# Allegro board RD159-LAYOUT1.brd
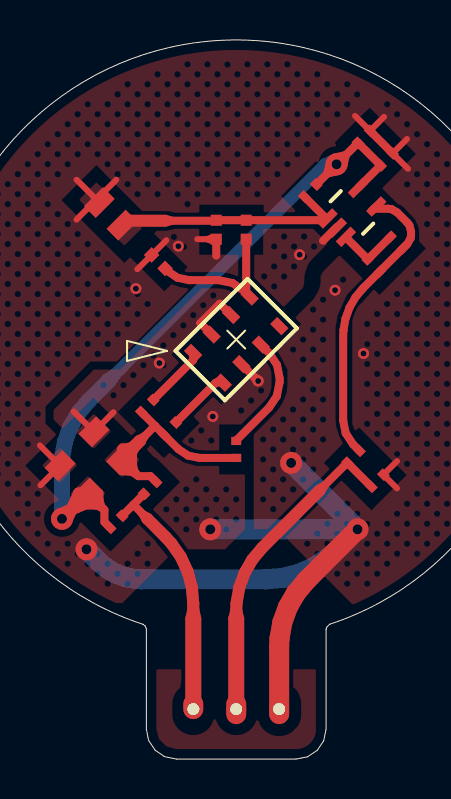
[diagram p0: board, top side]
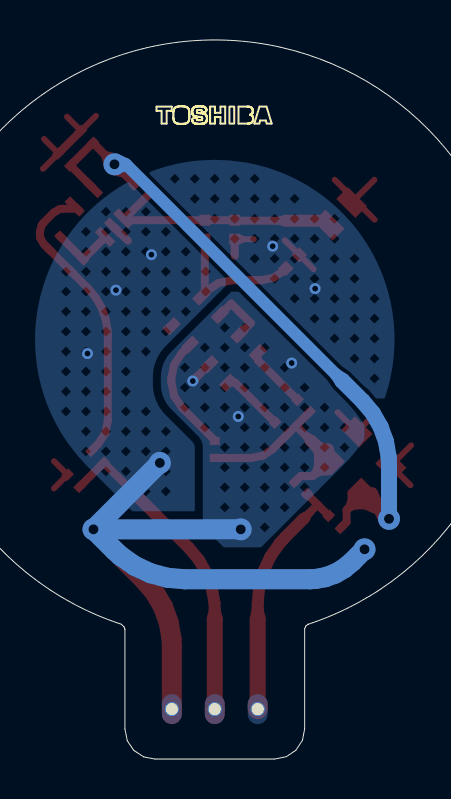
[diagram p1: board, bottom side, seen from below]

Outline 9.35 x 36 mm; copper layers: TOP, BOTTOM. Coordinates in mm from the lower left corner of the outline.
Outline path: 0,6.75 arc(4.67,36) 9.35,6.75 9.22,6.62 9.19,6.54 9.18,6.49 9.18,1.5 9.06,0.91 8.74,0.44 8.24,0.11 7.68,0 1.68,0 1.09,0.12 0.62,0.44 0.29,0.94 0.18,1.5 0.18,6.53 0.11,6.66 0.01,6.74 0,6.75

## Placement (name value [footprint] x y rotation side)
C1  -  [KC00060ATS01]  -1.76 15.7 315 top
C2  -  [DC834K0ACP]  12.7 25.84 315 top
C3  -  [KC00050ACF01]  11.75 13.93 225 top
C4  -  [KC00050ACF01]  12.21 30.02 225 top
C5  -  [KC00050ACF01]  11.08 31.15 225 top
C6  -  [KC00060ATS01]  -3.45 14 315 top
C7  -  [DC810K]  -1.61 27.3 135 top
NOREF  -  []  8.44 30.96 0 top
R1  -  [DR824K0ACF01]  4.68 15.5 90 top
R2  -  [DR824K0ACF01]  1.35 16.55 45 top
R3  -  [DR824K0ACF01]  0.22 17.68 45 top
R4  -  [KC00050ACF01]  0.36 13.57 225 top
R5  -  [DR824K0ACP]  11.57 24.71 315 top
R6  -  [DR824K0ACP]  -1.34 11.88 225 top
R7  -  [DR824K0ACF01]  10.55 15.13 225 top
R8  -  [KCK02021AKP]  5.18 26.5 90 top
R9  -  [KCK02021AKP]  3.68 26.5 270 top
R10  -  [KCK02021AKP]  0.78 24.9 135 top
R11  -  [KC00050ACP]  8.39 28.46 45 top
TP1  -  [DCK7F1]  2.53 2.5 0 top
TP2  -  [DCK7F1]  4.68 2.5 0 top
TP3  -  [DCK7F1]  6.83 2.5 0 top
U1  -  [LAP02741AKP]  4.68 21 45 top
U2  -  [MMS00380AKF]  10.47 27.36 315 top

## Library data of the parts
C1 C6 = GDM030002136: alternate symbols: (T:KC00060ATS01;B:KC00060BTS01,KC00060BFS01)
C2 = G36030133418: alternate symbols: (T:DC834K0ACP;B:DC834K0BCP)
C3 = GDM030000207: alternate symbols: (T:KC00050ACF01;B:KC00050BCF01)
C4 = GDM030002097: alternate symbols: (T:KC00050ACF01;B:KC00050BCF01)
C5 = GDM030002515: alternate symbols: (T:KC00050ACF01;B:KC00050BCF01)
C7 = GDM030000019: alternate symbols: (T:DC810K;B:DC910K)
R1-R3 R7 = GDM010001350: alternate symbols: (T:DR824K0ACF01;B:DR824K0BCF01)
R4 = GDM010003904: alternate symbols: (T:KC00050ACF01;B:KC00050BCF01)
R5 = G36010118169: alternate symbols: (T:DR824K0ACP;B:DR824K0BCP)
R6 = G36010118534: alternate symbols: (T:DR824K0ACP;B:DR824K0BCP)
R8-R10 = GDM010003025: alternate symbols: (T:KCK02021AKP;B:KCK02021BKP)
R11 = GDM010002207: alternate symbols: (T:KC00050ACP;B:KC00050BCP)
TP1-TP3 = DCK7F1: alternate symbols: (T:DCK7F1;B:DCK7B1)
U1 = K47S002B: alternate symbols: (T:LAP02741AKP;B:LAP02741BKP)
U2 = K47S002A: alternate symbols: (T:MMS00380AKF;B:MMS00380BKF)

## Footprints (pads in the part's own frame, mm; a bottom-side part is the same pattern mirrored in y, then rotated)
DC810K
  rect 0.83x1.35 smd: 1(-0.8,0) 2(0.8,0)
DC834K0ACP
  rect 0.41x0.5 smd: 1(-0.425,0) 2(0.425,0)
DCK7F1
  round 0.711 hole 0.6: 1(0,0)
DR824K0ACF01
  rect 0.41x0.5 smd: 1(-0.425,0) 2(0.425,0)
DR824K0ACP
  rect 0.41x0.5 smd: 1(-0.425,0) 2(0.425,0)
KC00050ACF01
  rect 0.41x0.5 smd: 1(-0.425,0) 2(0.425,0)
KC00050ACP
  rect 0.41x0.5 smd: 1(-0.425,0) 2(0.425,0)
KC00060ATS01
  rect 0.95x1.25 smd: 1(-0.975,0) 2(0.975,0)
KCK02021AKP
  rect 0.55x0.55 smd: 1(-0.475,0) 2(0.475,0)
LAP02741AKP
  rect 0.5x0.8 smd: 1(-2,1.05) 2(-0.69,1.05) 3(0.69,1.05) 4(2,1.05) 5(2,-1.05) 6(0.69,-1.05) 7(-0.69,-1.05) 8(-2,-1.05)
MMS00380AKF
  rect 0.4x1.05 smd: 1(-0.65,-1.075) 2(0,-1.075) 3(0.65,-1.075) 4(0.65,1.075) 5(-0.65,1.075)

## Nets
GND: C1.1(TP-1) C3.1(TP-1) C4.1(TP-1) C5.1(TP-1) C6.1(TP-1) C7.2(TP-1) R9.2(TP-1) R10.2(TP-1) TP3.1 U1.2 U1.3 U1.7 U2.2
VCC: R4.2(TP-1) R6.1(TP-1) TP1.1
SENS: C3.2(TP-1) R7.2(TP-1) TP2.1
SIG14: C4.2(TP-1) C5.2(TP-1) C6.2(TP-1) R6.2(TP-1) R11.2(TP-1) U2.5
SIG18: R8.1(TP-1) R10.1(TP-1) U1.4
SIG19: C7.1(TP-1) R8.2(TP-1) R9.1(TP-1) R11.1(TP-1) U2.1
SIG21: C2.1(TP-1) R5.1(TP-1) U1.5 U2.3
SIG22: C1.2(TP-1) R1.1(TP-1) R2.1(TP-1) R3.1(TP-1) R4.1(TP-1)
SIG23: C2.2(TP-1) R5.2(TP-1) R7.1(TP-1) U2.4
SIG26: R3.2(TP-1) U1.1
SIG27: R2.2(TP-1) U1.8
SIG28: R1.2(TP-1) U1.6

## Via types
v1: diameter 1.1, hole 0.5, TOP to BOTTOM, 6 vias
v2: diameter 0.55, hole 0.3, TOP to BOTTOM, 8 vias

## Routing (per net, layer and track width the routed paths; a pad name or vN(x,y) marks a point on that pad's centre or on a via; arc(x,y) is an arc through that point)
GND: length 64.5
  TOP w0.3: -3.46,17.4 C1.1 -1.47,17.36 ; 12.73,13.55 C3.1 12.73,14.91 ; 10.63,32.2 C5.1 12.08,32.15 ; 3.51,26.02 2.73,26.02 ; -5.15,15.7 C6.1 -5.12,13.71 ; -0.27,24.52 R10.2 1.18,25.97 ; C7.2 -2.32,28 ; -2.32,28 -3.32,27 ; -2.32,28 -3.32,29 ; -2.32,28 -1.33,29 ; 13.28,29.55 C4.1 13.23,31.04
  TOP w0.4: U1.3 3.85,22.8 2.88,21.82 U1.2 ; v2(5.78,18.93) 4.83,19.88 ; C5.1 C4.1 ; 9.72,26.64 9.03,25.95 ; R9.2 3.68,25.2
  TOP w0.508: R9.2 3.51,26.02
  TOP w1: v1(10.75,11.5) 8.2,8.95 7.68,8.32 7.27,7.61 6.99,6.84 6.84,6.04 6.83,5.63 TP3.1 6.83,2.25
  BOTTOM w1: v1(10.75,11.5) 9.72,10.46 9.39,10.17 8.68,9.67 7.89,9.3 7.05,9.08 6.18,9 -0.08,9 -0.34,9.01 -0.86,9.1 -1.35,9.28 -1.8,9.54 -2.2,9.88 v1(-2.82,10.5) ; v1(10.75,11.5) v1(7.43,14.82) ; v1(10.75,11.5) v1(3.38,11.5)
  vias: v2(-0.35,23.55) v2(0.83,19.82) v2(1.78,25.68) v2(3.5,17.15) v2(7.85,25.25) v2(9.63,23.48) v2(11.05,20.3)
VCC: length 12.8
  TOP w0.4: 0.23,12.03 -0.1,12.35 ; -0.47,12.74 -0.09,12.35 ; -0.47,12.74 0.06,13.27 ; -0.47,12.74 R6.1
  TOP w0.6: 0.23,12.03 1.15,11.1 1.43,10.8 1.9,10.13 2.24,9.39 2.45,8.59 2.53,7.78 2.53,7
  TOP w0.8: 2.53,2.75 2.53,7
  TOP w1: TP1.1 2.53,2.75
SENS: length 16.4
  TOP w0.4: C3.2 10.25,14.83 ; 8.85,13.45 10.24,14.84
  TOP w0.6: 4.68,7 4.68,7.42 4.69,7.81 4.83,8.58 5.09,9.31 5.48,9.99 5.98,10.58 8.85,13.45
  TOP w0.8: 4.68,2.75 4.68,7
  TOP w1: 4.68,2.75 TP2.1 4.68,2.25
SIG14: length 40.4
  TOP w0.4: -2.17,13.31 C6.2 -1.99,12.53 ; -2.75,12.7 -2.41,12.7 -2.25,12.67 -1.96,12.51 ; -1.96,12.51 -1.92,12.47 -1.92,11.86 -1.64,11.57 ; -1.96,12.51 -1.99,12.53 ; R11.2 v1(9.7,29.77) C5.2 C4.2 10.81,28.62 ; -1.99,12.53 -2.09,12.67 -2.17,12.98 -2.17,13.3
  TOP w0.6: v1(-4.05,12.03) -3.85,11.9 -3.2,13.3 C6.2 ; v1(-4.05,12.03) C6.2 ; v1(-4.05,12.03) -4.15,12.25 -2.75,12.85 C6.2
  BOTTOM w0.6: -1.72,18.93 9.13,29.77 v1(9.7,29.77)
  BOTTOM w0.8: -1.72,18.93 -2.73,17.92 -3.24,17.32 -3.63,16.64 -3.9,15.9 -4.03,15.13 -4.05,14.73 v1(-4.05,12.03)
SIG18: length 7.6
  TOP w0.4: R8.1 5.18,23.33 U1.4 5.06,23.45 4.49,23.83 3.78,23.98 2.32,23.98 1.74,24.09 1.26,24.41 R10.1
SIG19: length 12
  TOP w0.4: 9.26,27.1 9.13,26.98 R8.2 R9.1 ; 1.1,26.95 3.68,26.95 ; R11.1 9.19,27.05
  TOP w0.6: 1.1,26.95 -0.83,26.95 C7.1
SIG21: length 3.1
  TOP w0.4: C2.1 R5.1 10.18,26.11
SIG22: length 14.2
  TOP w0.4: -0.49,15.04 -0.49,14.69 -0.4,14.37 -0.3,14.24 ; -0.28,14.21 -0.3,14.24 ; -0.28,14.21 -0.23,14.16 0.38,14.16 R4.1 ; -0.28,14.21 -0.56,14.38 -0.73,14.4 -1.05,14.4 ; -0.3,14.24 C1.2 ; R3.1 0.61,16.68 ; 0.61,16.68 -0.15,15.93 ; 0.61,16.68 R2.1 1.78,15.51 2.26,15.19 2.84,15.07 R1.1
  TOP w0.6: -1,15.5 -0.84,15.5 -0.52,15.59 -0.39,15.69 -0.15,15.93 ; C1.2 -0.15,15.93 ; -0.15,15.92 -0.41,15.66 -0.58,15.38 -0.6,15.21 -0.6,14.8
SIG23: length 15.3
  TOP w0.4: U2.4 11.47,27.45 11.58,27.55 12.29,27.55 12.45,27.53 12.74,27.36 13.25,26.85 13.35,26.72 13.43,26.41 13.43,26.24 13.41,26.07 13.25,25.79 C2.2 R5.2 11.03,23.57 10.65,23.12 10.35,22.6 10.15,22.05 10.04,21.46 10.03,21.17 10.03,16.95 10.16,16.32 10.53,15.75 R7.1
SIG26: length 3.2
  TOP w0.4: U1.1 2.52,19.97 R3.2
SIG27: length 3.2
  TOP w0.4: R2.2 3.65,18.84 U1.8
SIG28: length 5.9
  TOP w0.4: 4.68,15.95 6.32,17.6 6.71,18.17 6.85,18.87 6.85,19.06 6.72,19.73 6.32,20.33 U1.6

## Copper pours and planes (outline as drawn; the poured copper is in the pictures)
GND on TOP: 5.58,25.18 5.6,25.23 5.65,25.25 6.03,25.25 6.03,26.48 6.05,26.53 6.1,26.55 8.49,26.55 8.52,26.54 8.55,26.53 9.21,25.87 9.23,25.81 9.21,25.76 8.53,25.07 8.33,24.85 8.23,24.65 8.1,24.25 8.08,23.83 8.07,23.82 8.03,23.62 8.02,23.6 8.01,23.58 7.1,22.68 7.05,22.66 7,22.68 5.6,24.08 5.58,24.1 5.58,24.13 ; 12 cut-outs
GND on TOP: outline of 151 points within -9.74,7.75 18.71,34.31 ; 591 cut-outs
GND on TOP: -3.3,16.35 -3.32,16.4 -3.3,16.45 -2.51,17.23 -2.46,17.26 -2.41,17.23 -1.64,16.47 -1.62,16.41 -1.64,16.36 -2.42,15.58 -2.47,15.56 -2.53,15.58
GND on TOP: 4.7,25.25 4.75,25.23 4.78,25.18 4.78,24.26 4.74,24.2 4.67,24.19 4.38,24.3 3.98,24.38 2.17,24.38 2.1,24.42 2.12,24.5 2.24,24.62 0.6,26.26 0.58,26.31 0.6,26.37 0.67,26.43 0.69,26.44 0.72,26.45 1.2,26.45 1.62,26.55 1.63,26.55 2.75,26.55 2.8,26.53 2.83,26.48 2.83,25.25 ; 2 cut-outs
GND on TOP: -3.15,27.95 -3.17,28 -3.15,28.05 -2.38,28.82 -2.32,28.84 -2.27,28.82 -1.5,28.05 -1.48,28 -1.5,27.95 -2.27,27.18 -2.32,27.16 -2.38,27.18
GND on TOP: -4.45,16.98 -4.47,17 -4.47,17.03 -4.47,17.44 -4.47,17.47 -4.45,17.5 -2.47,19.48 -2.45,19.49 -2.42,19.5 -1.14,19.5 2.9,23.54 2.93,23.56 2.96,23.56 3.75,23.56 4.04,23.54 4.06,23.53 4.32,23.45 4.43,23.39 4.47,23.33 4.45,23.27 1.43,20.25 1.77,19.9 1.79,19.85 1.77,19.8 1.65,19.68 1.63,19.64 0.88,18.89 0.83,18.87 0.77,18.89 0.51,19.15 -1.26,17.38 -0.38,16.49 -0.36,16.44 -0.38,16.38 -0.52,16.24 -0.57,16.22 -0.63,16.24 -2.45,18.06 -2.51,18.06 -3.97,16.6 -4.02,16.58 -4.08,16.6 ; 13 cut-outs
GND on TOP: -5,14.65 -5.02,14.7 -5,14.75 -4.21,15.53 -4.16,15.56 -4.11,15.53 -3.34,14.77 -3.32,14.71 -3.34,14.66 -4.12,13.88 -4.17,13.86 -4.23,13.88
GND on TOP: 5.04,14.25 5.09,14.23 5.11,14.18 5.11,11.53 5.11,11.5 5.09,11.48 4.14,10.52 4.11,10.51 4.08,10.5 2.29,10.5 2.26,10.51 2.23,10.53 1.75,11.2 1.46,11.53 0.54,12.45 0.52,12.5 0.54,12.55 1.86,13.88 0.66,15.08 0.61,15.08 0.58,15.1 0.23,15.45 0.21,15.5 0.23,15.55 0.29,15.62 0.34,15.67 0.39,15.69 0.44,15.67 1.05,15.06 1.29,15.3 1.34,15.32 1.39,15.3 1.44,15.25 1.47,15.23 2.03,14.87 2.08,14.84 2.65,14.68 2.7,14.68 3.75,14.68 3.8,14.65 3.83,14.6 3.83,14.25 ; 18 cut-outs
GND on TOP: 5.55,16.22 5.56,16.25 5.57,16.27 6.6,17.3 6.84,17.59 6.86,17.62 7.07,17.98 7.08,18.02 7.2,18.35 7.24,18.73 7.24,19.5 7.06,19.83 6.94,20.09 6.7,20.48 6.69,20.52 6.72,20.56 7.07,20.92 7.15,20.96 7.19,21 7.51,21.32 7.55,21.36 7.59,21.43 7.93,21.77 7.87,21.84 7.68,22.03 7.66,22.09 7.68,22.14 7.73,22.19 7.74,22.22 8.53,23 8.78,23.42 8.85,23.6 8.9,23.85 8.9,24.16 8.91,24.19 9,24.36 9.04,24.43 9.79,25.18 9.84,25.2 9.9,25.18 10.97,24.11 10.99,24.06 10.97,24 10.48,23.52 10.46,23.49 10.23,23.25 9.75,22.2 9.65,21.6 9.65,17.1 9.68,16.68 9.7,16.57 9.84,16.16 10,15.86 10.01,15.81 9.99,15.76 9.18,14.94 9.17,14.92 9.07,14.82 9.32,14.58 9.34,14.53 9.32,14.47 9.06,14.22 9.05,14.19 8.93,14.08 8.92,14.07 8.62,13.88 6.26,11.52 6.24,11.51 6.21,11.5 5.63,11.5 5.57,11.52 5.55,11.57 ; 44 cut-outs
GND on TOP: 6.45,18.77 6.35,18.31 6.09,17.92 4.94,16.77 4.92,16.76 4.89,16.75 3.83,16.75 3.83,15.52 3.8,15.47 3.75,15.45 3.13,15.45 3.12,15.45 2.78,15.47 2.77,15.48 2.52,15.54 2.48,15.56 2.26,15.67 2.24,15.68 2.04,15.82 1.99,15.86 1.97,15.91 1.99,15.96 2.85,16.82 2.58,17.1 2.56,17.15 2.58,17.2 3.47,18.1 3.53,18.12 3.58,18.1 3.93,17.75 4.25,18.07 4.26,18.1 4.29,18.12 4.33,18.14 4.37,18.17 4.68,18.49 4.72,18.54 4.77,18.62 6.05,19.9 6.1,19.92 6.15,19.9 6.37,19.57 6.45,19.19 ; 6 cut-outs
GND on BOTTOM: -2.86,18.62 -3,18.52 -3.38,18.08 -3.4,18.06 -3.43,18.05 -3.77,18.05 -3.82,18.06 -3.84,18.1 -3.07,25.59 3.13,29.87 3.92,29.97 3.93,29.97 4.67,30 4.68,30 5.45,29.97 6.68,29.77 7.87,29.41 7.91,29.4 7.95,29.34 7.93,29.28 3.38,24.72 3.36,24.71 -1.67,19.68 -1.68,19.67 -1.75,19.62 -2.1,19.38 -2.84,18.63 ; 50 cut-outs
GND on BOTTOM: 6.33,2.75 6.83,3.25 7.33,2.75 7.33,2.25 6.83,1.75 6.33,2.25
GND on BOTTOM: 5.28,11.68 5.27,11.65 5.25,11.63 4.25,10.62 4.22,10.61 4.19,10.6 2.39,10.6 2.36,10.61 2.34,10.62 -1.93,14.89 -2.39,15.43 -2.81,16.01 -2.82,16.03 -2.82,16.05 -2.82,16.7 -2.82,16.72 -2.81,16.74 -2.4,17.32 -2.4,17.33 -1.98,17.82 -1.97,17.83 -1.25,18.55 -0.95,18.97 -0.94,18.98 3.45,23.38 3.48,23.39 3.51,23.4 3.81,23.4 3.84,23.39 3.86,23.38 6.85,20.39 7.24,19.81 7.38,19.12 7.38,18.78 7.24,18.09 6.85,17.51 5.52,16.18 5.34,15.91 5.28,15.59 ; 58 cut-outs
GND on BOTTOM: 7.78,19.12 7.61,19.96 7.13,20.68 4.15,23.66 4.13,23.69 4.13,23.71 4.13,24.02 4.13,24.05 4.15,24.07 8.94,28.86 8.98,28.88 9.02,28.88 9.09,28.85 13.45,22.99 12.03,15.82 11.58,15.23 11.57,15.22 11.33,14.95 11.05,14.65 8.82,12.42 8.8,12.41 8.77,12.4 5.75,12.4 5.7,12.42 5.68,12.47 5.68,15.59 5.71,15.75 5.8,15.89 7.13,17.22 7.61,17.94 7.78,18.78 ; 76 cut-outs
VCC on BOTTOM: 2.03,2.75 2.53,3.25 3.03,2.75 3.03,2.25 2.53,1.75 2.03,2.25
Net_1 on TOP: 1.68,0.5 1.18,0.63 0.81,1 0.68,1.5 0.68,4.42 0.7,4.48 0.75,4.5 1.85,4.5 1.9,4.48 1.93,4.42 1.93,4.01 1.92,3.99 1.88,3.6 1.87,3.58 1.85,3.55 1.57,3.19 1.48,2.75 1.48,2.25 2.37,1.21 3.53,1.94 3.6,1.99 3.67,1.94 4.65,1.2 5.66,1.89 5.73,1.94 5.8,1.89 6.65,1.16 7.68,1.57 7.76,1.65 7.79,1.7 7.85,1.82 7.9,1.96 7.9,1.99 7.92,2.14 7.93,2.16 7.93,2.84 7.92,2.86 7.9,3 7.89,3.05 7.83,3.22 7.82,3.23 7.76,3.35 7.74,3.39 7.64,3.51 7.61,3.54 7.56,3.58 7.53,3.6 7.53,3.64 7.53,4.42 7.55,4.48 7.6,4.5 8.59,4.5 8.64,4.48 8.67,4.42 8.67,1.37 8.67,1.36 8.33,0.75 7.68,0.5
SENS on BOTTOM: 4.18,2.75 4.68,3.25 5.18,2.75 5.18,2.25 4.68,1.75 4.18,2.25
SIG14 on TOP: -3.57,13.25 -3.59,13.3 -3.57,13.35 -2.8,14.12 -2.75,14.14 -2.7,14.12 -1.93,13.35 -1.91,13.3 -1.93,13.25 -2.7,12.48 -2.75,12.46 -2.8,12.48
SIG19 on TOP: -1.73,26.51 -1.76,26.56 -1.73,26.62 -0.95,27.4 -0.9,27.42 -0.85,27.4 -0.09,26.64 -0.07,26.59 -0.09,26.53 -0.87,25.75 -0.92,25.73 -0.98,25.75
SIG22 on TOP: -1.88,14.93 -1.91,14.99 -1.88,15.04 -1.1,15.82 -1.05,15.84 -1,15.82 -0.21,15.04 -0.19,14.99 -0.21,14.93 -1,14.15 -1.05,14.13 -1.1,14.15

Small or netless copper shapes (teardrops, artwork), in the pictures only: 10 on TOP, 2 on BOTTOM

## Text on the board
SYMBOL-2-BOTTOM: GROVE-AS | V | S | G
User.6: R3 | R6 | R4 | R2 | U1 | LED | R11 | PD | C5 | R7 | C3 | C4 | R9 | R8 | R1 | C6 | C1 | C7 | R10 | U2 | R5 | C2
